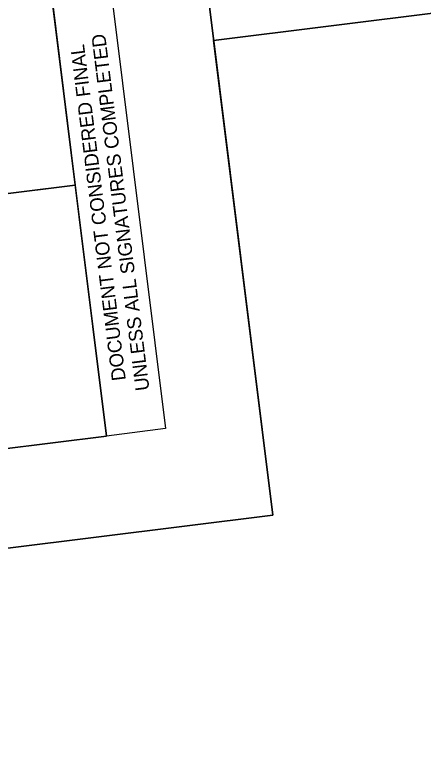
# Model space of a CAD drawing. Extents: x 2367685 to 2368979, y 807242 to 809048.
# Drawn here: x 2367846.4 to 2368008.2, y 808586.6 to 808884.8 of the extents above; entities that cross this region are included whole.
import ezdxf

# ---------------------------------------------------------------- set-up
doc = ezdxf.new("R2010")
doc.units = 0
for name, color, linetype in [('Old_Level_10', 7, 'Continuous'), ('Old_Level_2', 7, 'Continuous'), ('Old_Level_22', 7, 'Continuous'), ('Plan Sheet CELL', 7, 'Continuous'), ('Plot Shape CELL', 7, 'Continuous')]:
    doc.layers.add(name, color=color, linetype=linetype)

msp = doc.modelspace()

# ---------------------------------------------------------------- linework, layer by layer
at = {"layer": 'Old_Level_10'}
for points in [[(2367894.53, 807409.74), (2368936.44, 807539.65), (2368750.87, 809028.13), (2367918.8, 808924.4), (2367948.4, 808686.99), (2367738.54, 808660.82)], [(2367948.4, 808686.99), (2367918.8, 808924.42), (2367708.93, 808898.29), (2367738.54, 808660.82)]]:
    msp.add_lwpolyline(points, close=True, dxfattribs=at)
at = {"layer": 'Old_Level_2'}
msp.add_lwpolyline([(2368930.25, 807589.27), (2368757.06, 808978.53), (2367924.99, 808874.8), (2367948.4, 808686.99), (2367738.54, 808660.82), (2367888.32, 807459.37)], close=True, dxfattribs=at)
at = {"layer": 'Old_Level_22'}
msp.add_lwpolyline([(2368826.65, 807671.15), (2368834.5, 807611.56), (2368735.93, 807593.18), (2368175.69, 807520.89), (2367878.85, 807535.48), (2367738.54, 808660.82), (2367948.4, 808686.99), (2367924.99, 808874.8), (2368757.06, 808978.53), (2368918.62, 807682.61)], close=True, dxfattribs=at)
msp.add_lwpolyline([(2368826.65, 807671.15), (2368834.5, 807611.56), (2368735.93, 807593.18), (2368175.69, 807520.89), (2367878.85, 807535.48), (2367738.54, 808660.82), (2367948.4, 808686.99), (2367924.99, 808874.8), (2368757.06, 808978.53), (2368918.62, 807682.61)], close=True, dxfattribs=at)
at = {"layer": 'Plan Sheet CELL'}
for p, q in [((2367881.16, 808919.72), (2367905.9, 808721.22)), ((2367881.16, 808919.72), (2367905.9, 808721.22)), ((2367882.58, 808718.31), (2367857.84, 808916.81)), ((2367882.58, 808718.31), (2367857.84, 808916.81)), ((2367905.9, 808721.22), (2367882.58, 808718.31)), ((2367905.9, 808721.22), (2367882.58, 808718.31))]:
    msp.add_line(p, q, dxfattribs=at)
at = {"layer": 'Plot Shape CELL'}
msp.add_line((2367758.58, 808803.66), (2367870.18, 808817.59), dxfattribs=at)
for points in [[(2368936.44, 807539.65), (2367894.53, 807409.74), (2367733.67, 808699.73), (2367882.58, 808718.31), (2367857.85, 808916.81), (2368750.87, 809028.14)], [(2367758.58, 808803.66), (2367746.2, 808902.88), (2367857.85, 808916.81), (2367870.23, 808817.58)], [(2367770.96, 808704.38), (2367758.58, 808803.66), (2367870.23, 808817.58), (2367882.58, 808718.31)]]:
    msp.add_lwpolyline(points, close=True, dxfattribs=at)

# ---------------------------------------------------------------- texts
at = {"layer": 'Plan Sheet CELL'}
for s, p in [('UNLESS ALL SIGNATURES COMPLETED', (2367899.6, 808736.55)), ('UNLESS ALL SIGNATURES COMPLETED', (2367899.6, 808736.55)), ('DOCUMENT NOT CONSIDERED FINAL', (2367890.24, 808740.5)), ('DOCUMENT NOT CONSIDERED FINAL', (2367890.24, 808740.5))]:
    msp.add_text(s, height=5.5, rotation=97.1063, dxfattribs=at).set_placement(p)

doc.saveas('drawing.dxf')
